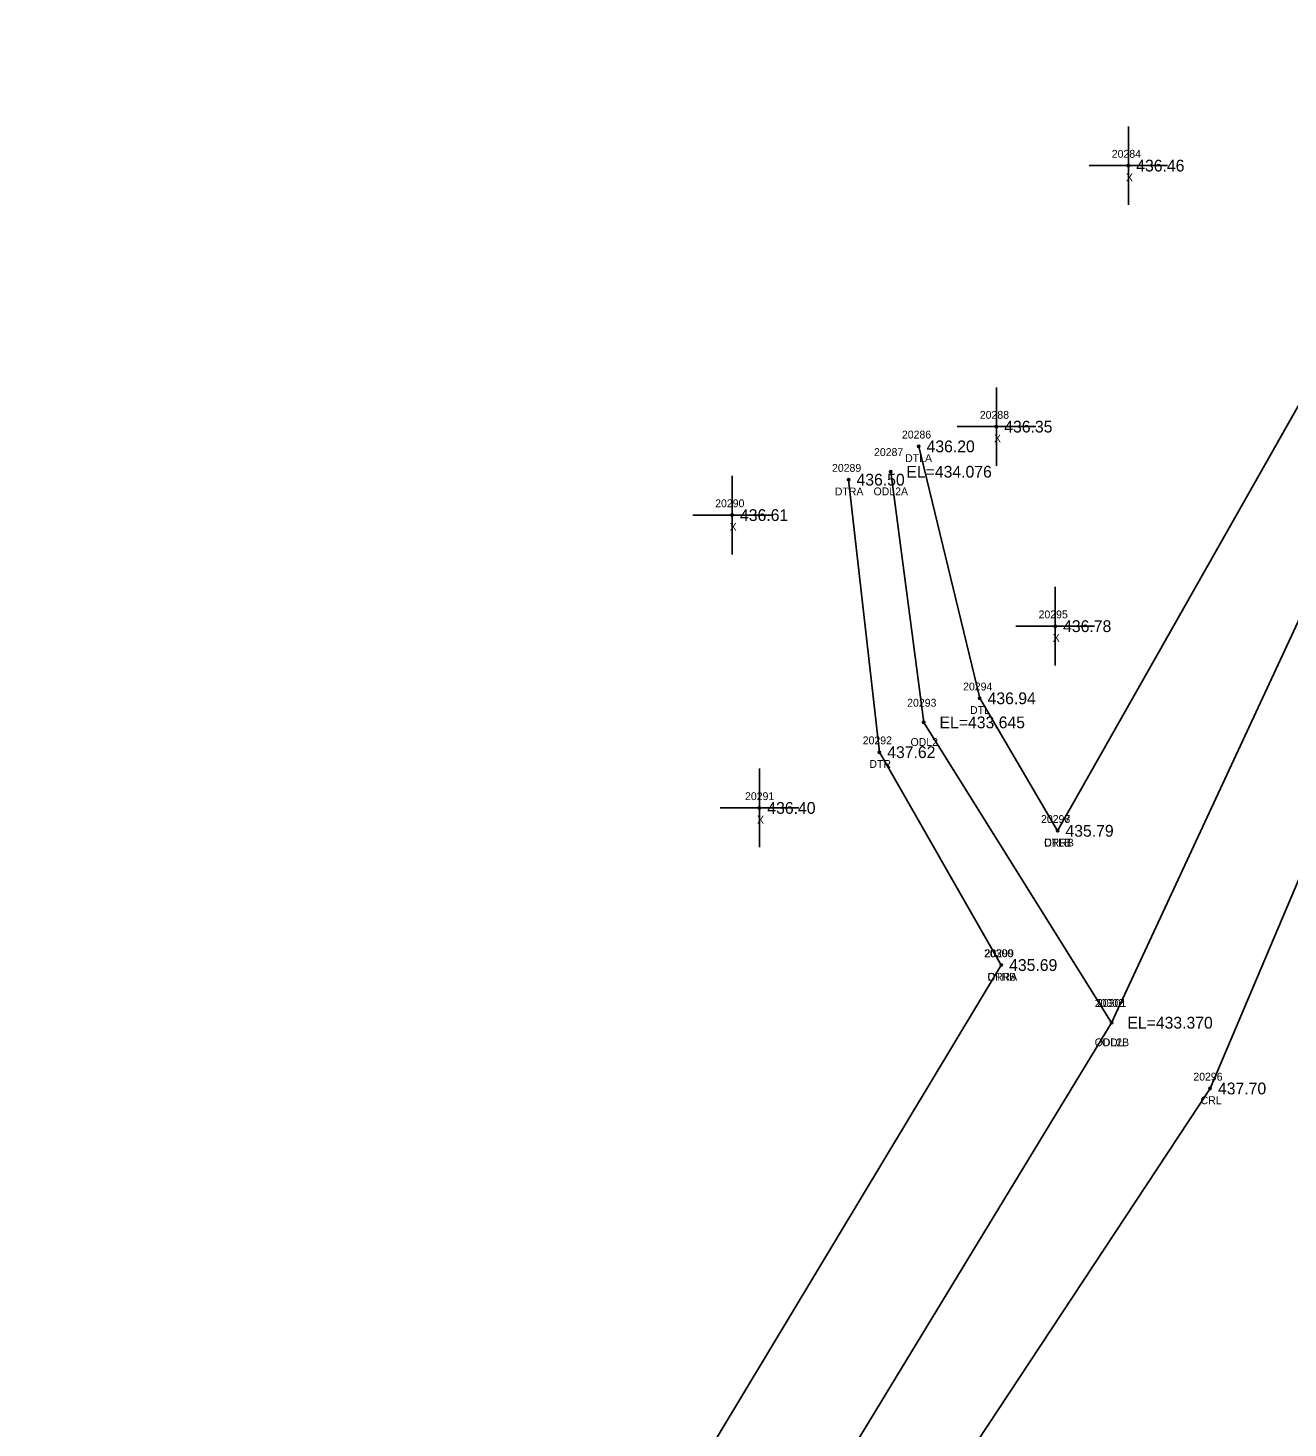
# Model space of a CAD drawing. Extents: x 1797709 to 1799052, y 896018 to 896955.
# Drawn here: x 1798378.7 to 1798539.1, y 896576.7 to 896754.9 of the extents above; entities that cross this region are included whole.
import ezdxf

# ---------------------------------------------------------------- set-up
doc = ezdxf.new("R2010")
doc.units = 0
for name, color, linetype in [('RD_EX_H2O', 7, 'Continuous'), ('RD_EX_H2O_txCode', 7, 'Continuous'), ('RD_EX_Misc', 7, 'Continuous'), ('RD_EX_Misc_txCode', 7, 'Continuous'), ('RD_EX_TX_H2O_ELEV', 7, 'Continuous'), ('RD_EX_TX_Misc_ELEV', 7, 'Continuous'), ('RD_SMD_Locator', 7, 'Continuous')]:
    doc.layers.add(name, color=color, linetype=linetype)

msp = doc.modelspace()

# ---------------------------------------------------------------- linework, layer by layer
at = {"layer": 'RD_EX_H2O'}
for points in [[(1798652.43, 896917.58), (1798601.94, 896827.15), (1798558.78, 896718.92), (1798516.66, 896628.32), (1798463.08, 896540.21), (1798439.21, 896521.86), (1798389.85, 896497.35), (1798369.72, 896471.55), (1798343.52, 896433.35), (1798291.39, 896374.31), (1798235.39, 896326.89), (1798184.99, 896269.63), (1798095.18, 896198.01), (1798023.89, 896139.85)], [(1798638.77, 896915.93), (1798589.91, 896831.16), (1798551.08, 896725.68), (1798509.78, 896652.75)], [(1798663.68, 896911.94), (1798617.01, 896821.94), (1798571.81, 896720.45), (1798529.2, 896619.95), (1798471.21, 896532.04), (1798459.45, 896520.86)], [(1798492.1, 896701.69), (1798499.87, 896669.62), (1798509.78, 896652.75)], [(1798488.53, 896698.46), (1798492.75, 896666.55), (1798516.66, 896628.32)], [(1798483.18, 896697.45), (1798487.09, 896662.76), (1798502.61, 896635.66)], [(1798502.61, 896635.66), (1798452.16, 896551.79), (1798380.86, 896504.02), (1798360.17, 896479.84), (1798335.44, 896438.68), (1798277.37, 896387.2), (1798228.36, 896339.61), (1798175.66, 896278.7), (1798083.83, 896204.11), (1798020.11, 896146.19)]]:
    msp.add_lwpolyline(points, dxfattribs=at)
at = {"layer": 'RD_EX_Misc'}
for p, q in [((1798518.79, 896732.43), (1798518.79, 896742.43)), ((1798513.79, 896737.43), (1798523.79, 896737.43)), ((1798501.99, 896699.2), (1798501.99, 896709.2)), ((1798496.99, 896704.2), (1798506.99, 896704.2)), ((1798468.35, 896687.94), (1798468.35, 896697.94)), ((1798463.35, 896692.94), (1798473.35, 896692.94)), ((1798509.48, 896673.8), (1798509.48, 896683.8)), ((1798504.48, 896678.8), (1798514.48, 896678.8)), ((1798471.83, 896650.66), (1798471.83, 896660.66)), ((1798466.83, 896655.66), (1798476.83, 896655.66))]:
    msp.add_line(p, q, dxfattribs=at)
at = {"layer": 'RD_SMD_Locator'}
for centre in [(1798518.79, 896737.43), (1798501.99, 896704.2), (1798492.1, 896701.69), (1798488.53, 896698.46), (1798483.18, 896697.45), (1798468.35, 896692.94), (1798509.48, 896678.8), (1798499.87, 896669.62), (1798492.75, 896666.55), (1798487.09, 896662.76), (1798471.83, 896655.66), (1798509.78, 896652.75), (1798509.78, 896652.75), (1798502.61, 896635.66), (1798502.61, 896635.66), (1798516.66, 896628.32), (1798516.66, 896628.32), (1798529.2, 896619.95)]:
    msp.add_circle(centre, 0.15, dxfattribs=at)

# ---------------------------------------------------------------- texts
at = {"layer": 'RD_EX_H2O_txCode'}
for s, p in [('20286', (1798489.96, 896702.69)), ('20287', (1798486.41, 896700.46)), ('DTLA', (1798490.37, 896699.69)), ('20289', (1798481.06, 896698.45)), ('DTRA', (1798481.42, 896695.45)), ('ODL2A', (1798486.35, 896695.46)), ('20294', (1798497.75, 896670.62)), ('20293', (1798490.63, 896668.55)), ('DTL', (1798498.63, 896667.62)), ('20292', (1798484.97, 896663.76)), ('ODL2', (1798491.06, 896663.55)), ('DTR', (1798485.82, 896660.76)), ('20297', (1798507.67, 896653.75)), ('20298', (1798507.67, 896653.75)), ('CRRB', (1798508.06, 896650.75)), ('DTLB', (1798508.07, 896650.75)), ('20300', (1798500.41, 896636.66)), ('20299', (1798500.49, 896636.66)), ('CRRA', (1798500.86, 896633.66)), ('DTRB', (1798500.86, 896633.66)), ('20302', (1798514.51, 896630.32)), ('20301', (1798514.79, 896630.32)), ('ODL2B', (1798514.5, 896625.32)), ('ODL', (1798515.42, 896625.32)), ('20296', (1798527.06, 896620.95)), ('CRL', (1798527.98, 896617.95))]:
    msp.add_text(s, height=1, dxfattribs=at).set_placement(p)
at = {"layer": 'RD_EX_Misc_txCode'}
for s, p in [('20284', (1798516.68, 896738.43)), ('X', (1798518.48, 896735.43)), ('20288', (1798499.88, 896705.2)), ('X', (1798501.68, 896702.2)), ('20290', (1798466.19, 896693.94)), ('X', (1798468.03, 896690.94)), ('20295', (1798507.36, 896679.8)), ('X', (1798509.16, 896676.8)), ('20291', (1798469.99, 896656.66)), ('X', (1798471.51, 896653.66))]:
    msp.add_text(s, height=1, dxfattribs=at).set_placement(p)
at = {"layer": 'RD_EX_TX_H2O_ELEV'}
for s, p in [('436.20', (1798493.1, 896700.94)), ('EL=434.076', (1798490.53, 896697.71)), ('436.50', (1798484.18, 896696.7)), ('436.94', (1798500.87, 896668.87)), ('EL=433.645', (1798494.75, 896665.8)), ('437.62', (1798488.09, 896662.01)), ('435.79', (1798510.78, 896652)), ('435.79', (1798510.78, 896652)), ('435.69', (1798503.61, 896634.91)), ('435.69', (1798503.61, 896634.91)), ('EL=433.370', (1798518.66, 896627.57)), ('EL=433.370', (1798518.66, 896627.57)), ('437.70', (1798530.2, 896619.2))]:
    msp.add_text(s, height=1.5, dxfattribs=at).set_placement(p)
at = {"layer": 'RD_EX_TX_Misc_ELEV'}
for s, p in [('436.46', (1798519.79, 896736.68)), ('436.35', (1798502.99, 896703.45)), ('436.61', (1798469.35, 896692.19)), ('436.78', (1798510.48, 896678.05)), ('436.40', (1798472.83, 896654.91))]:
    msp.add_text(s, height=1.5, dxfattribs=at).set_placement(p)

doc.saveas('drawing.dxf')
